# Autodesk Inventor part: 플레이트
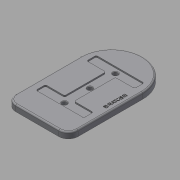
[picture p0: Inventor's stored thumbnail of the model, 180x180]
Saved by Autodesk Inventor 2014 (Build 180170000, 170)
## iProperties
Created: 2016-08
Part Number: 플레이트
Material: 알루미늄 6061
Document SubType Name: Modeling
Designer: mduedu
Density: 2.71 g/cm^3
Appearance: 기본값
Mass: 881.522 g
Surface Area: 629.196 cm^2
Volume: 325.285 cm^3
Author: mduedu
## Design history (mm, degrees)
sketch "스케치1" dims "d0" = 220, "d2" = 130
  geometry: L1 (110, 65)-(-45, 65); L2 (-45, 65)-(-45, -65); L3 (-45, -65)-(110, -65); L4 (45, -65)-(45, 65); L5 (45, 65)-(-45, -65); L6 (-45, 65)-(45, -65); L7 (110, -65)-(110, 65); 5 further points
  constraints: 14 end point, 5 midpoint, 3 parallel, 2 point on line, 2 vertical alignment, 1 coincident, 1 horizontal, 1 perpendicular, 1 vertical, 4 other
extrude "돌출1" new body sketch "스케치1" distance "d3" = 13; taper "d4" = 0 deg
sketch "스케치2"
  geometry: L1 (-63, -50)-(63, -50); L2 (63, -50)-(63, 50); L3 (63, 50)-(-63, 50); L4 (-63, 50)-(-63, -50); L5 (-63, -50)-(63, 50); L6 (63, -50)-(-63, 50); L7 (-63, 50)-(-43, 50); L8 (-43, 50)-(-43, -50); L9 (-43, -50)-(-63, -50); L10 (-63, -50)-(-63, 50); L11 (63, 50)-(43, 50); L12 (43, 50)-(43, -50); L13 (43, -50)-(63, -50); L14 (63, -50)-(63, 50); L15 (-43, -10)-(43, -10); L16 (43, -10)-(43, 10); L17 (43, 10)-(-43, 10); L18 (-43, 10)-(-43, -10); L19 (-43, -10)-(43, 10); L20 (43, -10)-(-43, 10); 1 further point
  constraints: 40 end point, 8 parallel, 4 horizontal, 4 midpoint, 4 perpendicular, 3 point on line
  dimensions: "d18" = 126 distance of L3.end L2.end; "d19" = 100 distance of L2.end L1.end; "d20" = 20 distance of L8.end L9.end; "d21" = 20 distance of L12.end L13.end (= d20); "d22" = 20 distance of L15.end L16.end
extrude "돌출3" cut sketch "스케치2" distance "d23" = 3; taper "d24" = 0 deg
fillet "모깎기6" dims "d25" = 3
sketch "스케치4"
  geometry: L1 (-40, -10)-(40, -10) reference; L2 (43, -13)-(43, -47) reference; L3 (40, 10)-(-40, 10) reference; L4 (-43, 13)-(-43, 47) reference; L5 (45, -65)-(-110, -65) reference; L6 (-110, 65)-(45, 65) reference; L7 (-53, 40)-(-53, -40); L8 (53, 40)-(53, -40); L9 (-53, 0)-(53, 0); L10 (-46, 50)-(-60, 50) reference; L11 (-63, 47)-(-63, -47) reference; L12 (-60, -50)-(-46, -50) reference; L13 (-43, -47)-(-43, -13) reference; L14 (46, -50)-(60, -50) reference; L15 (63, -47)-(63, 47) reference; L16 (60, 50)-(46, 50) reference; L17 (43, 47)-(43, 13) reference; L18 (-110, -65)-(-110, 65) reference; C1 r 5 at (-53, 0); C2 r 5 at (0, 0); C3 r 5 at (53, 0); A1 r 3 centre (-40, -13) between (-40, -10) and (-43, -13) reference; A2 r 3 centre (40, -13) between (43, -13) and (40, -10) reference; A3 r 3 centre (40, 13) between (40, 10) and (43, 13) reference; A4 r 3 centre (-40, 13) between (-43, 13) and (-40, 10) reference; A5 r 65 centre (45, 0) between (45, -65) and (45, 65) reference; A6 r 3 centre (-46, 47) between (-43, 47) and (-46, 50) reference; A7 r 3 centre (-60, 47) between (-60, 50) and (-63, 47) reference; A8 r 3 centre (-60, -47) between (-63, -47) and (-60, -50) reference; A9 r 3 centre (-46, -47) between (-46, -50) and (-43, -47) reference; A10 r 3 centre (46, -47) between (43, -47) and (46, -50) reference; A11 r 3 centre (60, -47) between (60, -50) and (63, -47) reference; A12 r 3 centre (60, 47) between (63, 47) and (60, 50) reference; A13 r 3 centre (46, 47) between (46, 50) and (43, 47) reference; 1 further point
  constraints: 6 end point, 3 centre point, 3 coincident, 2 midpoint, 1 parallel, 1 perpendicular
  dimensions: "d26" = 10 diameter of C1; "d27" = 10 diameter of C2; "d28" = 10 diameter of C3
extrude "돌출4" cut sketch "스케치4" stored distance "d29" = 3; taper "d30" = 0 deg
chamfer "모따기2" distance "d31" = 1; stored, may be unused: second distance "d32" = 2, angle "d33" = 45 deg
fillet "모깎기7" dims "d34" = 20
fillet "모깎기1" dims "d14" = 3
sketch "스케치3"
  geometry: L1 (-90, -65)-(45, -65) reference; 3 further points
  constraints: 1 vertical alignment, 1 other
  dimensions: "d15" = 12 distance from line of point (0, -53) L1
feature "엠보싱1" sketch "스케치3" dims "d16" = 0.5, "d17" = 0
node "솔리드1"
node "절단 모서리 투영1"
